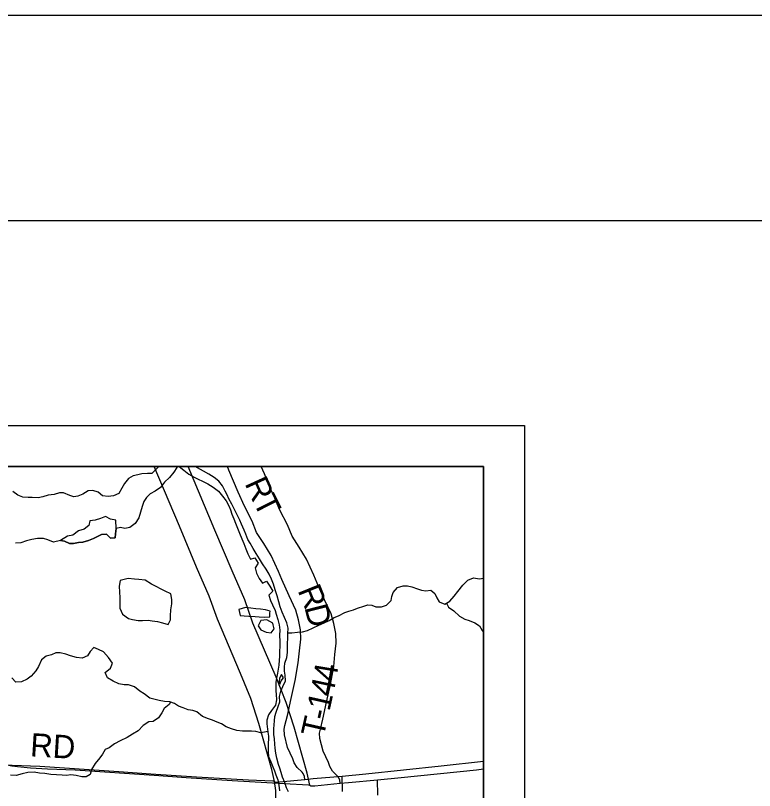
# Model space of a CAD drawing. Extents: x -38.2 to 41.9, y -4 to 24.9.
# Drawn here: x 7.758 to 9.561, y 20.109 to 22 of the extents above; entities that cross this region are included whole.
import ezdxf

# ---------------------------------------------------------------- set-up
doc = ezdxf.new("R2010")
doc.units = 0
for name, color, linetype in [('GM_X_County_Road', 7, 'Continuous'), ('GM_X_County_Road_Text', 7, 'Continuous'), ('GM_X_Interchange_Ramps', 7, 'Continuous'), ('GM_X_Major_River', 7, 'Continuous'), ('GM_X_Minor_Lake', 7, 'Continuous'), ('GM_X_Minor_River', 7, 'Continuous'), ('GM_X_State_Location', 7, 'Continuous'), ('GM_X_State_Route', 7, 'Continuous'), ('GM_X_Township_Road', 7, 'Continuous'), ('GM_X_Township_Road_Text', 7, 'Continuous'), ('SH_Border', 7, 'Continuous'), ('SH_Cut_Line', 7, 'Continuous'), ('SH_Data', 7, 'Continuous')]:
    doc.layers.add(name, color=color, linetype=linetype)

msp = doc.modelspace()

# ---------------------------------------------------------------- linework, layer by layer
at = {"layer": 'GM_X_County_Road'}
for points in [[(7.2308, 20.2032), (7.2643, 20.202), (7.2751, 20.2027), (7.2839, 20.2043), (7.2984, 20.2073), (7.3177, 20.2124), (7.3677, 20.2248), (7.3838, 20.2275), (7.3947, 20.2283), (7.4077, 20.2275), (7.4212, 20.2258), (7.526, 20.2061), (7.6117, 20.1892), (7.662, 20.1791), (7.6761, 20.177), (7.7074, 20.1743), (7.7496, 20.1716), (7.817, 20.1689), (8.01, 20.1556), (8.0878, 20.1504), (8.1996, 20.1432), (8.3267, 20.1356), (8.386, 20.1327), (8.3896, 20.1314)], [(8.484, 20.1384), (8.555, 20.1445), (8.6124, 20.1501), (8.7964, 20.1693), (8.9, 20.181)], [(8.3896, 20.1314), (8.3923, 20.1301), (8.394, 20.1298), (8.3958, 20.1297), (8.3975, 20.13), (8.4018, 20.1304), (8.4637, 20.1366), (8.484, 20.1384)]]:
    msp.add_lwpolyline(points, dxfattribs=at)
at = {"layer": 'GM_X_Interchange_Ramps'}
for points in [[(5.6874, 16.3954), (5.9853, 16.3764), (6.413, 16.3602), (6.4263, 16.3595), (7.1336, 16.3198), (7.3442, 16.3107), (7.5793, 16.2961), (7.6901, 16.2894), (7.9696, 16.2752), (8.9, 16.2272), (8.9, 17.7063), (8.9, 17.9093), (8.9, 20.9), (5.1243, 20.9)], [(5.7739, 16.3862), (6.0718, 16.3672), (6.4995, 16.351), (6.5128, 16.3503), (7.2201, 16.3106), (7.4307, 16.3015), (7.6658, 16.2869), (7.7766, 16.2803), (8.0561, 16.266), (8.9, 16.2225), (8.9, 20.9), (5.2114, 20.9)], [(8.4761, 20.1222), (8.4694, 20.1514), (8.4376, 20.2637), (8.4182, 20.3243), (8.3936, 20.3859), (8.337, 20.518), (8.3171, 20.5747), (8.2861, 20.6451), (8.2445, 20.7448), (8.1787, 20.9)]]:
    msp.add_lwpolyline(points, dxfattribs=at)
at = {"layer": 'GM_X_Major_River'}
for points in [[(8.1571, 20.9), (8.1689, 20.8907), (8.1809, 20.8815), (8.1934, 20.8742), (8.2032, 20.8692), (8.2137, 20.8642), (8.2269, 20.8573), (8.2405, 20.8493), (8.2529, 20.8393), (8.2627, 20.8275), (8.2721, 20.8161), (8.2781, 20.8039), (8.2822, 20.7944), (8.2859, 20.7834), (8.2904, 20.772), (8.2945, 20.7617), (8.2997, 20.7496), (8.3042, 20.737), (8.3097, 20.723), (8.3146, 20.7116), (8.3202, 20.699), (8.325, 20.6865), (8.3314, 20.6736), (8.342, 20.6769), (8.3499, 20.664), (8.343, 20.6523), (8.3455, 20.6394), (8.3523, 20.6268), (8.3602, 20.6154), (8.3704, 20.6202), (8.3787, 20.6077), (8.3861, 20.5955), (8.3759, 20.5861), (8.3803, 20.5728), (8.3852, 20.5625), (8.3912, 20.5488), (8.3937, 20.5394), (8.3982, 20.5264), (8.4011, 20.5135), (8.403, 20.5002), (8.4021, 20.4885), (8.4024, 20.4733), (8.4027, 20.4597), (8.4023, 20.4502), (8.4022, 20.4366), (8.401, 20.4271), (8.4005, 20.415), (8.399, 20.4055), (8.3974, 20.396), (8.395, 20.3835), (8.3931, 20.3726), (8.393, 20.3631), (8.3933, 20.3528), (8.394, 20.3434), (8.3947, 20.3308), (8.3923, 20.318), (8.3824, 20.3044), (8.3748, 20.2942), (8.3709, 20.2813), (8.3709, 20.2719), (8.3727, 20.259), (8.3741, 20.2457)], [(8.2745, 20.8305), (8.2692, 20.84), (8.2632, 20.8525), (8.2542, 20.864), (8.2426, 20.8728), (8.2297, 20.8808), (8.2169, 20.8885), (8.2015, 20.8965), (8.1963, 20.9)], [(8.4236, 20.1062), (8.4187, 20.1161), (8.4146, 20.1294), (8.4094, 20.1423), (8.4057, 20.1537), (8.4027, 20.1636), (8.3998, 20.1731), (8.3957, 20.1883), (8.3931, 20.2005), (8.3917, 20.2126), (8.3906, 20.2228), (8.3899, 20.2353), (8.3885, 20.246), (8.3878, 20.26), (8.3886, 20.2699), (8.3895, 20.2793), (8.391, 20.2903), (8.3941, 20.3005), (8.3988, 20.3141), (8.403, 20.3259), (8.4023, 20.3391), (8.405, 20.3516), (8.4104, 20.3634), (8.4166, 20.377), (8.4159, 20.391), (8.4144, 20.4005), (8.4141, 20.41), (8.4146, 20.4202), (8.4196, 20.4338), (8.4215, 20.4463), (8.4212, 20.4588), (8.4213, 20.4683), (8.4221, 20.4808), (8.4222, 20.4925), (8.4231, 20.5054), (8.4197, 20.5183), (8.4138, 20.5316), (8.4089, 20.5442), (8.4037, 20.5579), (8.4004, 20.57), (8.3963, 20.5844), (8.3915, 20.5993), (8.387, 20.6126), (8.3825, 20.6247), (8.3766, 20.6369), (8.3691, 20.6494), (8.3601, 20.662), (8.3533, 20.6742), (8.3451, 20.6879), (8.3376, 20.6997), (8.3301, 20.7126), (8.3249, 20.7221), (8.32, 20.7347), (8.3156, 20.7446), (8.3096, 20.7594), (8.3055, 20.7689), (8.2988, 20.7818), (8.2924, 20.7947), (8.2853, 20.8081), (8.2786, 20.821), (8.2745, 20.8305)], [(8.4068, 20.3922), (8.4022, 20.3839), (8.4014, 20.3744), (8.4029, 20.3691)], [(8.4029, 20.3691), (8.4063, 20.3766), (8.4117, 20.3846), (8.4068, 20.3922)], [(8.3741, 20.2457), (8.3748, 20.2426), (8.3747, 20.2176), (8.3742, 20.204), (8.3753, 20.1922), (8.3809, 20.1793), (8.3861, 20.1675), (8.3898, 20.1576), (8.3932, 20.1481), (8.398, 20.1352), (8.4002, 20.1227), (8.4016, 20.109)]]:
    msp.add_lwpolyline(points, dxfattribs=at)
at = {"layer": 'GM_X_Minor_Lake'}
for points in [[(8.0031, 20.7485), (8.0027, 20.7686), (7.9894, 20.7717), (7.9773, 20.7781), (7.9648, 20.7732), (7.952, 20.7686), (7.9387, 20.7675), (7.9365, 20.7557), (7.9255, 20.747), (7.9115, 20.7425), (7.8979, 20.7322), (7.8846, 20.7299), (7.8676, 20.7197)], [(7.8676, 20.7197), (7.8774, 20.7178), (7.8892, 20.7121), (7.899, 20.7117), (7.9115, 20.7144), (7.9221, 20.7155), (7.9357, 20.7193), (7.9478, 20.7246), (7.9577, 20.7288), (7.9675, 20.7337), (7.98, 20.7345), (7.9894, 20.725), (8.0008, 20.7262), (8.0019, 20.7356), (8.0031, 20.7485)], [(8.139, 20.5741), (8.139, 20.5753), (8.1371, 20.5893), (8.1231, 20.5961), (8.1129, 20.6003), (8.1011, 20.6068), (8.0898, 20.6124), (8.0742, 20.6227), (8.0587, 20.6238), (8.0481, 20.6246), (8.033, 20.6268), (8.0133, 20.6219)], [(8.0133, 20.6219), (8.0103, 20.6079), (8.0114, 20.5935), (8.0126, 20.5802), (8.0126, 20.5541), (8.019, 20.54), (8.0334, 20.529), (8.0433, 20.5268), (8.0569, 20.5245), (8.0678, 20.5241), (8.0811, 20.5249), (8.0909, 20.5237), (8.1046, 20.5218), (8.1163, 20.5181), (8.1299, 20.5146), (8.1356, 20.5256), (8.136, 20.5355), (8.1371, 20.5499), (8.139, 20.5647), (8.139, 20.5741)], [(8.3788, 20.5419), (8.3789, 20.5469), (8.3676, 20.5503), (8.3554, 20.5522), (8.3441, 20.553), (8.3324, 20.5541), (8.3191, 20.5556), (8.3025, 20.5507)], [(8.3025, 20.5507), (8.3059, 20.5367), (8.3157, 20.5359), (8.3274, 20.5351), (8.3422, 20.5336), (8.3524, 20.5329), (8.3657, 20.5321), (8.3785, 20.5333), (8.3788, 20.5419)], [(8.3566, 20.5245), (8.3502, 20.5113), (8.3562, 20.5018), (8.3698, 20.4961), (8.382, 20.4942), (8.3888, 20.5037), (8.3867, 20.5132)], [(8.3867, 20.5132), (8.3857, 20.5177), (8.371, 20.5257), (8.3566, 20.5245)]]:
    msp.add_lwpolyline(points, dxfattribs=at)
at = {"layer": 'GM_X_Minor_River'}
for points in [[(8.1073, 20.9), (8.1014, 20.8938), (8.0901, 20.8831), (8.0798, 20.8828), (8.0662, 20.882), (8.056, 20.8797), (8.045, 20.8771), (8.0333, 20.8702), (8.0235, 20.8585), (8.0174, 20.8471), (8.0098, 20.8342), (7.9966, 20.8285), (7.9837, 20.8263), (7.9701, 20.8281), (7.9591, 20.8372), (7.9466, 20.8414), (7.9353, 20.8407), (7.9224, 20.8327), (7.9099, 20.8278), (7.9001, 20.8255), (7.8899, 20.8289), (7.8751, 20.8353), (7.8649, 20.8357), (7.852, 20.8315), (7.8373, 20.83), (7.8244, 20.8262), (7.8127, 20.8236), (7.7983, 20.8243), (7.7885, 20.824), (7.7752, 20.8251), (7.7631, 20.8296), (7.751, 20.8391)], [(8.1539, 20.9), (8.1517, 20.8972), (8.1445, 20.8858), (8.1336, 20.8729), (8.1211, 20.8615), (8.1116, 20.849), (8.0984, 20.8399), (8.0863, 20.8335), (8.0776, 20.824), (8.0712, 20.8145), (8.0666, 20.802), (8.0628, 20.7884), (8.0583, 20.7747), (8.05, 20.7611), (8.0364, 20.7508), (8.0243, 20.7489), (8.014, 20.7512), (8.0031, 20.7485), (8.0019, 20.7356), (8.0008, 20.7262), (7.9894, 20.725), (7.98, 20.7345), (7.9675, 20.7337), (7.9577, 20.7288), (7.9478, 20.7246), (7.9357, 20.7193), (7.9221, 20.7155), (7.9115, 20.7144), (7.899, 20.7117), (7.8892, 20.7121), (7.8774, 20.7178), (7.8676, 20.7197), (7.8506, 20.7152), (7.8369, 20.7212), (7.826, 20.7242), (7.8112, 20.7239), (7.7976, 20.7216), (7.7843, 20.7182), (7.7707, 20.714), (7.7575, 20.7125)], [(8.4223, 20.4942), (8.4319, 20.4942), (8.4463, 20.4957), (8.458, 20.4969), (8.4705, 20.4995), (8.4841, 20.506), (8.4981, 20.5124), (8.5114, 20.5181), (8.5231, 20.5238), (8.5356, 20.5314), (8.5458, 20.5356), (8.5617, 20.5435), (8.5715, 20.5469), (8.5829, 20.55), (8.5927, 20.5541), (8.6078, 20.5595), (8.6177, 20.5621), (8.6275, 20.5617), (8.6374, 20.5579), (8.6506, 20.5576), (8.6631, 20.5614), (8.6744, 20.5727), (8.6763, 20.5826), (8.679, 20.5925), (8.6896, 20.605), (8.704, 20.6088), (8.7142, 20.6088), (8.7248, 20.6061), (8.7384, 20.6012), (8.7482, 20.5985), (8.7588, 20.5966), (8.7717, 20.5985), (8.7815, 20.5902), (8.7861, 20.5792), (8.7914, 20.5697), (8.8058, 20.5644), (8.8179, 20.5712), (8.8285, 20.5838), (8.8372, 20.5948), (8.8493, 20.6103), (8.8614, 20.6228), (8.8754, 20.6281), (8.8905, 20.6262), (8.9, 20.6274)], [(8.8097, 20.5666), (8.8148, 20.5568), (8.8277, 20.5474), (8.841, 20.5345), (8.8546, 20.5273), (8.8648, 20.5239), (8.8784, 20.5186), (8.8902, 20.511), (8.897, 20.5), (8.9, 20.496)], [(8.3733, 20.2532), (8.3695, 20.2527), (8.3567, 20.2501), (8.3442, 20.2535), (8.334, 20.2542), (8.323, 20.2539), (8.3113, 20.2542), (8.298, 20.2561), (8.2851, 20.2603), (8.2719, 20.2648), (8.2605, 20.2724), (8.2499, 20.2758), (8.2382, 20.2808), (8.2284, 20.2845), (8.214, 20.2902), (8.2, 20.3012), (8.1902, 20.3046), (8.1788, 20.3065), (8.1667, 20.3111), (8.1553, 20.3156), (8.1455, 20.3217), (8.1341, 20.3255), (8.1216, 20.3266), (8.1084, 20.3289), (8.0986, 20.3312), (8.0857, 20.3346), (8.0717, 20.3452), (8.0611, 20.352), (8.0478, 20.3626), (8.0331, 20.3675), (8.0229, 20.3675), (8.01, 20.3694), (7.996, 20.3759), (7.9824, 20.3846), (7.9763, 20.3975), (7.9896, 20.4081), (7.9948, 20.4202), (7.985, 20.4343), (7.9721, 20.4475), (7.9604, 20.4532), (7.9487, 20.4581), (7.94, 20.4483), (7.9332, 20.438), (7.9203, 20.4324), (7.9067, 20.4339), (7.8923, 20.438), (7.8809, 20.4418), (7.8669, 20.4456), (7.856, 20.4452), (7.8457, 20.4407), (7.8329, 20.4369), (7.8208, 20.4282), (7.814, 20.4119), (7.8072, 20.4016), (7.7962, 20.3887), (7.7863, 20.3808), (7.7727, 20.3743), (7.7587, 20.3736), (7.7489, 20.3846)], [(8.1357, 20.3249), (8.1326, 20.319), (8.1205, 20.3099), (8.1145, 20.2993), (8.1065, 20.2864), (8.0933, 20.2781), (8.0834, 20.2773), (8.0694, 20.2679), (8.0573, 20.255), (8.0433, 20.2466), (8.0301, 20.2387), (8.0131, 20.2303), (7.9994, 20.2235), (7.9866, 20.2136), (7.9764, 20.2091), (7.9703, 20.1985), (7.9631, 20.189), (7.9522, 20.1757), (7.9435, 20.1606), (7.9401, 20.1488), (7.9302, 20.1431), (7.9192, 20.1431), (7.9056, 20.1462), (7.8931, 20.1481), (7.8825, 20.1458), (7.8712, 20.1465), (7.8579, 20.148), (7.8443, 20.1488), (7.8296, 20.1511), (7.8163, 20.1518), (7.8031, 20.1545), (7.7876, 20.1534), (7.7739, 20.1499), (7.7592, 20.1461), (7.7455, 20.1465)]]:
    msp.add_lwpolyline(points, dxfattribs=at)
at = {"layer": 'GM_X_State_Location'}
for points in [[(8.5501, 20.1274), (8.5496, 20.1343), (8.546, 20.1419), (8.5438, 20.1448), (8.5314, 20.1567), (8.5245, 20.1677), (8.5213, 20.1774), (8.5082, 20.2055), (8.5005, 20.2363), (8.4999, 20.2495), (8.5017, 20.2592), (8.5077, 20.2833), (8.517, 20.3246), (8.5266, 20.3684), (8.5344, 20.4119), (8.537, 20.4413), (8.5404, 20.4691), (8.5397, 20.4921), (8.535, 20.5165), (8.5282, 20.5403), (8.5119, 20.5748), (8.4939, 20.615), (8.4861, 20.6344), (8.4677, 20.6739), (8.45, 20.7032), (8.4325, 20.73), (8.4217, 20.7574), (8.403, 20.7937), (8.3878, 20.8284), (8.3759, 20.8547), (8.3651, 20.8818), (8.3576, 20.9)], [(8.6419, 20.0979), (8.6415, 20.1353)]]:
    msp.add_lwpolyline(points, dxfattribs=at)
at = {"layer": 'GM_X_State_Route'}
for points in [[(8.3896, 20.1314), (8.3829, 20.1606), (8.3512, 20.2729), (8.3317, 20.3335), (8.3071, 20.3951), (8.2506, 20.5272), (8.2306, 20.5839), (8.1996, 20.6543), (8.158, 20.754), (8.0961, 20.9)], [(8.3935, 20.0658), (8.393, 20.1096), (8.3896, 20.1314)]]:
    msp.add_lwpolyline(points, dxfattribs=at)
at = {"layer": 'GM_X_Township_Road'}
for points in [[(8.4637, 20.1366), (8.4631, 20.1435), (8.4595, 20.1511), (8.4573, 20.154), (8.4449, 20.1659), (8.438, 20.1769), (8.4348, 20.1866), (8.4217, 20.2147), (8.414, 20.2455), (8.4134, 20.2587), (8.4153, 20.2684), (8.4212, 20.2925), (8.4305, 20.3338), (8.4401, 20.3776), (8.4479, 20.4211), (8.4505, 20.4504), (8.4539, 20.4783), (8.4532, 20.5013), (8.4485, 20.5257), (8.4417, 20.5495), (8.4254, 20.584), (8.4074, 20.6242), (8.3996, 20.6436), (8.3813, 20.6831), (8.3635, 20.7124), (8.3461, 20.7392), (8.3352, 20.7666), (8.3165, 20.8029), (8.3014, 20.8376), (8.2894, 20.8639), (8.2786, 20.891), (8.2749, 20.9)], [(8.5554, 20.1071), (8.555, 20.1445)]]:
    msp.add_lwpolyline(points, dxfattribs=at)
at = {"layer": 'GM_X_Township_Road_Text'}
for points in [[(7.3173, 20.194), (7.3507, 20.1928), (7.3616, 20.1935), (7.3704, 20.1951), (7.3849, 20.1981), (7.4042, 20.2032), (7.4542, 20.2157), (7.4703, 20.2183), (7.4812, 20.2191), (7.4942, 20.2183), (7.5077, 20.2166), (7.6125, 20.1969), (7.6982, 20.1801), (7.7484, 20.1699), (7.7626, 20.1678), (7.7939, 20.1651), (7.8361, 20.1624), (7.9035, 20.1597), (8.0965, 20.1465), (8.1743, 20.1412), (8.2861, 20.134), (8.4132, 20.1264), (8.4725, 20.1235), (8.4761, 20.1222)], [(8.5704, 20.1292), (8.6415, 20.1353), (8.6989, 20.1409), (8.8828, 20.1601), (8.9, 20.1621)], [(8.4761, 20.1222), (8.4788, 20.1209), (8.4805, 20.1206), (8.4823, 20.1205), (8.484, 20.1208), (8.4883, 20.1212), (8.5501, 20.1274), (8.5704, 20.1292)]]:
    msp.add_lwpolyline(points, dxfattribs=at)
at = {"layer": 'SH_Border'}
msp.add_lwpolyline([(1.5, 21.5), (33.5, 21.5), (33.5, 0.5), (1.5, 0.5)], close=True, dxfattribs=at)
at = {"layer": 'SH_Cut_Line'}
msp.add_lwpolyline([(0, 0), (34, 0), (34, 22), (0, 22)], close=True, dxfattribs=at)
msp.add_lwpolyline([(5.6874, 16.3954), (5.9853, 16.3764), (6.413, 16.3602), (6.4263, 16.3595), (7.1336, 16.3198), (7.3442, 16.3107), (7.5793, 16.2961), (7.6901, 16.2894), (7.9696, 16.2752), (8.9, 16.2272), (8.9, 17.7063), (8.9, 17.9093), (8.9, 20.9), (2.1103, 20.9)], dxfattribs=at)
at = {"layer": 'SH_Data'}
for p, q in [((2, 21), (9, 21)), ((9, 21), (9, 14)), ((2.1, 20.9), (8.9, 20.9)), ((8.9, 20.9), (8.9, 17.9093))]:
    msp.add_line(p, q, dxfattribs=at)

# ---------------------------------------------------------------- texts
at = {"layer": 'GM_X_County_Road_Text'}
msp.add_text('RD', height=0.05682, rotation=356.5467, dxfattribs=at).set_placement((7.7924, 20.193))
at = {"layer": 'GM_X_Township_Road_Text'}
for s, rotation, p in [('R', 294.4642, (8.3162, 20.8586)), ('T', 296.6324, (8.3365, 20.814)), ('R', 292.029, (8.4456, 20.5978)), ('D', 284.326, (8.4625, 20.5564)), ('4', 80.474, (8.5393, 20.3728)), ('4', 78.1571, (8.5316, 20.336)), ('1', 77.5139, (8.5239, 20.3012)), ('-', 77.3609, (8.5188, 20.2783)), ('T', 77.3183, (8.5094, 20.2368))]:
    msp.add_text(s, height=0.0568, rotation=rotation, dxfattribs=at).set_placement(p)

doc.saveas('drawing.dxf')
